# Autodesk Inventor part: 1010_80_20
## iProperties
Created: 2009-11
Part Number: 1010_80_20
Document SubType Name: Modeling
Designer: PN
Density: 2.71 g/cm^3
Material: Aluminum-6061
Mass: 19.709 g
Surface Area: 59.6867 cm^2
Volume: 7.2727 cm^3
Width: 1.000 in
Height: 1.000 in
Length: 1.000 in
Author: PN
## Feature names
1. Extrusion1
